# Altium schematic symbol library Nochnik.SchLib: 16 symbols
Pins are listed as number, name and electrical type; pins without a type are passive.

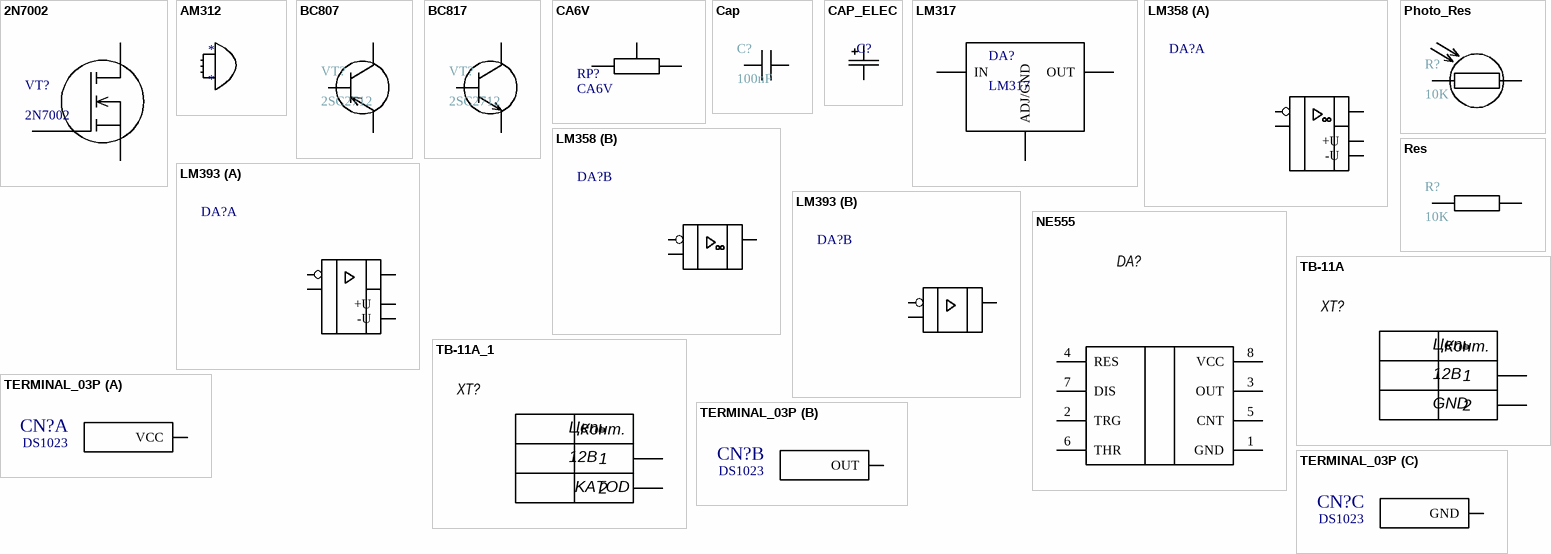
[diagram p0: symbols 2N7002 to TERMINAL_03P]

## 2N7002
designator VT?
footprint 2N7002
pins: 1 D, 2 G, 3 S

## AM312
designator *
pins: GND, OUT, VCC

## BC807
designator VT?, comment 2SC2712
footprint BC807
pins: B 10, E 11, С 9

## BC817
designator VT?, comment 2SC2712
footprint BC817
pins: B 10, E 11, С 9

## CA6V
designator RP?
Trimmer potentiometer CA6V; Value: 10k
footprint PR
pins: 1 2, 2, 3

## Cap
designator C?, comment 100nF
footprint C0805
footprint CAP0805
pins: 1 61, 2 62

## CAP_ELEC
designator C?
footprint CAP_ELEC_6.3*11
footprint CAP_ELEC_8*11
footprint CAP_ELECTROLIT
pins: 1, 2

## LM317
designator DA?
SOT-223
footprint SOT-223
pins: 1 IN, 2 OUT, 3 ADJ/GND

## LM358
designator DA?
LM358, SO8; Model: ОУ LM358A TEXAS INSTRUMENTS
footprint LM358
part A pins: 1 NetOUT "Информационный вход Х6", 2 "Информационный вход Х6", 3 "Информационный вход Х6", 4 -U "Информационный вход Х6", 8 +U "Информационный вход Х6"
part B pins: 5 "Информационный вход Х6", 6 "Информационный вход Х6", 7 "Информационный вход Х6"

## LM393
designator DA?
LM358, SO8; Model: ОУ LM358A TEXAS INSTRUMENTS
footprint LM393
part A pins: 1 "Информационный вход Х6", 2 "Информационный вход Х6", 3 "Информационный вход Х6", 4 -U "Информационный вход Х6", 8 +U "Информационный вход Х6"
part B pins: 5 "Информационный вход Х6", 6 "Информационный вход Х6", 7 "Информационный вход Х6"

## NE555
designator DA?
NE555, SOIC8; Model: Таймер NE555DR TEXAS INSTRUMENTS
footprint NE555
pins: 1 GND, 2 TRG, 3 OUT, 4 RES, 5 CNT, 6 THR, 7 DIS, 8 VCC

## Photo_Res
designator R?, comment 10K
footprint Photo_Res
pins: 1 2, 2

## Res
designator R?, comment 10K
footprint Res
pins: 1 2, 2

## TB-11A
designator XT?  (value not drawn)
Клеммник 2-контактный, 5мм, прямой; Sig1: Signal1; Sig2: Signal2; InMOP: 0; Current: 10 А; Voltage: 250 В
footprint TB-11A
pins: 1, 2

## TB-11A_1
designator XT?, comment TB-11A  (value not drawn)
Клеммник 2-контактный, 5мм, прямой; Sig1: Signal1; Sig2: Signal2; InMOP: 0; Current: 10 А; Voltage: 250 В
footprint TB-11A
pins: 1, 2

## TERMINAL_03P
designator CN?, comment DS1023
DS1023-1x4
footprint PLS-3
part A pins: 1 VCC
part B pins: 2 OUT
part C pins: 3 GND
